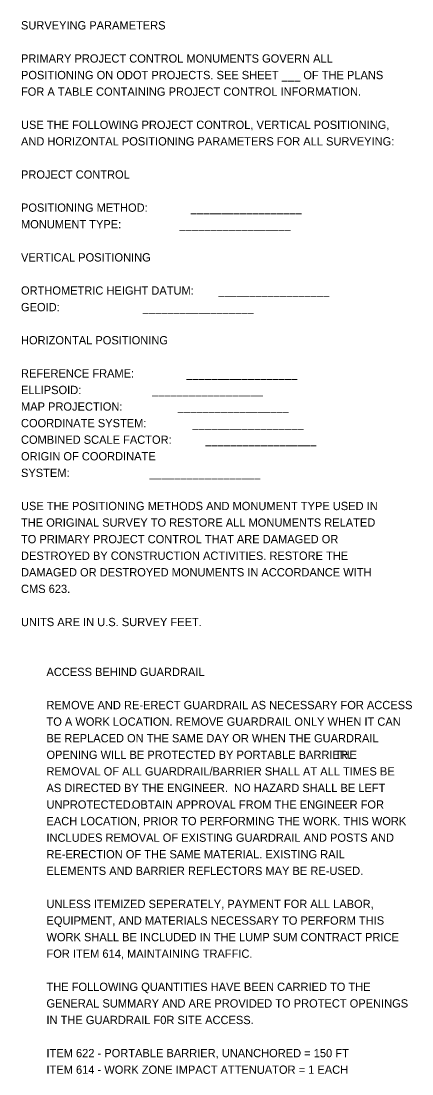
# Model space of a CAD drawing. Extents: x -15.3 to 74.8, y -11.5 to 47.6.
# Drawn here: x 34.82 to 41.44, y 4.14 to 21.92 of the extents above; entities that cross this region are included whole.
import ezdxf

# ---------------------------------------------------------------- set-up
doc = ezdxf.new("R2010")
doc.units = 0
doc.layers.add('SH_Text', color=7, linetype='Continuous')

msp = doc.modelspace()

# ---------------------------------------------------------------- texts
at = {"layer": 'SH_Text'}
for s, p in [('SURVEYING PARAMETERS', (34.824, 21.781)), ('PRIMARY PROJECT CONTROL MONUMENTS GOVERN ALL', (34.824, 21.221)), ('POSITIONING ON ODOT PROJECTS. SEE SHEET ___ OF THE PLANS', (34.824, 20.941)), ('FOR A TABLE CONTAINING PROJECT CONTROL INFORMATION.', (34.824, 20.661)), ('USE THE FOLLOWING PROJECT CONTROL, VERTICAL POSITIONING,', (34.824, 20.101)), ('AND HORIZONTAL POSITIONING PARAMETERS FOR ALL SURVEYING:', (34.824, 19.821)), ('PROJECT CONTROL', (34.824, 19.261)), ('POSITIONING METHOD:              __________________', (34.824, 18.701)), ('MONUMENT TYPE:                   __________________', (34.824, 18.421)), ('VERTICAL POSITIONING', (34.824, 17.861)), ('ORTHOMETRIC HEIGHT DATUM:        __________________', (34.824, 17.301)), ('GEOID:                           __________________', (34.824, 17.021)), ('HORIZONTAL POSITIONING', (34.824, 16.461)), ('REFERENCE FRAME:                 __________________', (34.824, 15.901)), ('ELLIPSOID:                       __________________', (34.824, 15.621)), ('MAP PROJECTION:                  __________________', (34.824, 15.341)), ('COORDINATE SYSTEM:               __________________', (34.824, 15.061)), ('COMBINED SCALE FACTOR:           __________________', (34.824, 14.781)), ('ORIGIN OF COORDINATE', (34.824, 14.501)), ('SYSTEM:                          __________________', (34.824, 14.221)), ('USE THE POSITIONING METHODS AND MONUMENT TYPE USED IN', (34.824, 13.661)), ('THE ORIGINAL SURVEY TO RESTORE ALL MONUMENTS RELATED', (34.824, 13.381)), ('TO PRIMARY PROJECT CONTROL THAT ARE DAMAGED OR', (34.824, 13.101)), ('DESTROYED BY CONSTRUCTION ACTIVITIES. RESTORE THE', (34.824, 12.821)), ('DAMAGED OR DESTROYED MONUMENTS IN ACCORDANCE WITH', (34.824, 12.541)), ('CMS 623.', (34.824, 12.261)), ('UNITS ARE IN U.S. SURVEY FEET.', (34.824, 11.701)), ('ACCESS BEHIND GUARDRAIL', (35.255, 10.858)), ('REMOVE AND RE-ERECT GUARDRAIL AS NECESSARY FOR ACCESS ', (35.255, 10.298)), ('TO A WORK LOCATION. REMOVE GUARDRAIL ONLY WHEN IT CAN ', (35.255, 10.018)), ('BE REPLACED ON THE SAME DAY OR WHEN THE GUARDRAIL', (35.255, 9.738)), ('OPENING WILL BE PROTECTED BY PORTABLE BARRIER. ', (35.255, 9.458)), ('THE ', (40.131, 9.458)), ('REMOVAL OF ALL GUARDRAIL/BARRIER SHALL AT ALL TIMES BE ', (35.255, 9.178)), ('AS DIRECTED BY THE ENGINEER.  NO HAZARD SHALL BE LEFT ', (35.255, 8.898)), ('UNPROTECTED. ', (35.255, 8.618)), ('OBTAIN APPROVAL FROM THE ENGINEER FOR ', (36.699, 8.618)), ('EACH LOCATION, PRIOR TO PERFORMING THE WORK. THIS WORK ', (35.255, 8.338)), ('INCLUDES REMOVAL OF EXISTING GUARDRAIL AND POSTS AND ', (35.255, 8.058)), ('RE-ERECTION OF THE SAME MATERIAL. EXISTING RAIL ', (35.255, 7.778)), ('ELEMENTS AND BARRIER REFLECTORS MAY BE RE-USED.', (35.255, 7.498)), ('UNLESS ITEMIZED SEPERATELY, PAYMENT FOR ALL LABOR, ', (35.255, 6.938)), ('EQUIPMENT, AND MATERIALS NECESSARY TO PERFORM THIS ', (35.255, 6.658)), ('WORK SHALL BE INCLUDED IN THE LUMP SUM CONTRACT PRICE ', (35.255, 6.378)), ('FOR ITEM 614, MAINTAINING TRAFFIC.', (35.255, 6.098)), ('THE FOLLOWING QUANTITIES HAVE BEEN CARRIED TO THE ', (35.255, 5.538)), ('GENERAL SUMMARY AND ARE PROVIDED TO PROTECT OPENINGS ', (35.255, 5.258)), ('IN THE GUARDRAIL F0R SITE ACCESS.', (35.255, 4.978)), ('ITEM 622 - PORTABLE BARRIER, UNANCHORED = 150 FT', (35.255, 4.418)), ('ITEM 614 - WORK ZONE IMPACT ATTENUATOR = 1 EACH', (35.255, 4.138))]:
    msp.add_text(s, height=0.14, dxfattribs=at).set_placement(p)

doc.saveas('drawing.dxf')
